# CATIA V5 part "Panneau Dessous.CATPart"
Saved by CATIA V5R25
Part number: Panneau Dessous
Bounding box of the stored display mesh (mm): x -160 to 160, y -55 to 55, z 0 to 3
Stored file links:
  C:\Users\m000605\Desktop\Projet FAB liseuse\Panneau Dessous.CATPart
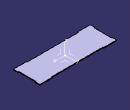
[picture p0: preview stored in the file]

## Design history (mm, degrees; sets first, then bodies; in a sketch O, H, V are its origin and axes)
AxisSystem1: origin (0, 0, 0), X (1, 0, 0), Y (0, 1, 0), Z (0, 0, 1)
Set1
  Sketch1 on XY plane of AxisSystem1, origin (0, 0, 0), H (1, 0, 0), V (0, 1, 0)
    line L1 (-107, 55) -> (-107, 52)
    line L2 (-107, 52) -> (107, 52)
    line L3 (107, 52) -> (107, 55)
    line L4 (107, 55) -> (160, 55)
    line L5 (160, 55) -> (160, 35)
    line L6 (160, 35) -> (157, 35)
    line L7 (157, 35) -> (157, -35)
    line L8 (160, -35) -> (157, -35)
    line L9 (160, -35) -> (160, -55)
    line L10 (160, -55) -> (107, -55)
    point P11 (107, -55)
    line L11 (107, -55) -> (107, -52)
    line L12 (107, -52) -> (-107, -52)
    point P13 (-107, -52)
    line L13 (-107, -52) -> (-107, -55)
    point P14 (-107, -55)
    line L14 (-107, -55) -> (-160, -55)
    line L15 (-160, -55) -> (-160, -35)
    point P16 (-160, -35)
    line L16 (-160, -35) -> (-157, -35)
    line L17 (-157, -35) -> (-157, 35)
    point P18 (-157, 35)
    line L18 (-157, 35) -> (-160, 35)
    point P19 (-160, 35)
    line L19 (-160, 35) -> (-160, 55)
    point P20 (-160, 55)
    line L20 (-160, 55) -> (-107, 55)
    reference intersected line E1 through (0, 0) direction (0, 1) from YZ plane of AxisSystem1
    reference projected line E2 through (0, 0) direction (1, 0) from edge [XY plane of AxisSystem1 | ZX plane of AxisSystem1]
    reference intersected line E3 through (0, 0) direction (0, 1) from YZ plane of AxisSystem1
    reference intersected line E4 through (0, 0) direction (0, 1) from YZ plane of AxisSystem1
    reference intersected line E5 through (0, 0) direction (-1, 0) from ZX plane of AxisSystem1
    reference projected line E6 through (0, 0) direction (0, 1) from edge [YZ plane of AxisSystem1 | XY plane of AxisSystem1]
    distance L19 L5 = 320
    distance L10 L4 = 110
    distance L7 L5 = 3
    distance L2 L4 = 3
    distance L16 L18 = 70
    distance L3 L5 = 53
    vertical: L1 V, L3 V, L5 V, L7 V, L9 V, L11 V, L13 V, L15 V, L17 V, L19 V
    horizontal: L2 H, L4 H, L6 H, L8 H, L10 H, L12 H, L14 H, L16 H, L18 H, L20 H
    coincidence: P11 L3, P13 L1, P14 L10, P16 L8, P18 L6, P19 L15, P20 L4
    symmetry: L17 L7 E1, L12 L2 H, L4 L10 H, L14 L20 E2, L19 L5 E3, L15 L9 E4, L16 L18 E5, L1 L3 E6
Body1 (main body)
  Pad1: profile Sketch1, direction (0, 0, 1), length 3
